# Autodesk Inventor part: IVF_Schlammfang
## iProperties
Created: 2009-02
Part Number: IVF_Schlammfang
Document SubType Name: Blech
Designer: Strathkötter
Density: 1 g/cm^3
Mass: 122.218 g
Surface Area: 1651.07 cm^2
Volume: 122.218 cm^3
Author: Strathkötter
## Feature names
1. Extrusion2
2. Ausklinkung1
